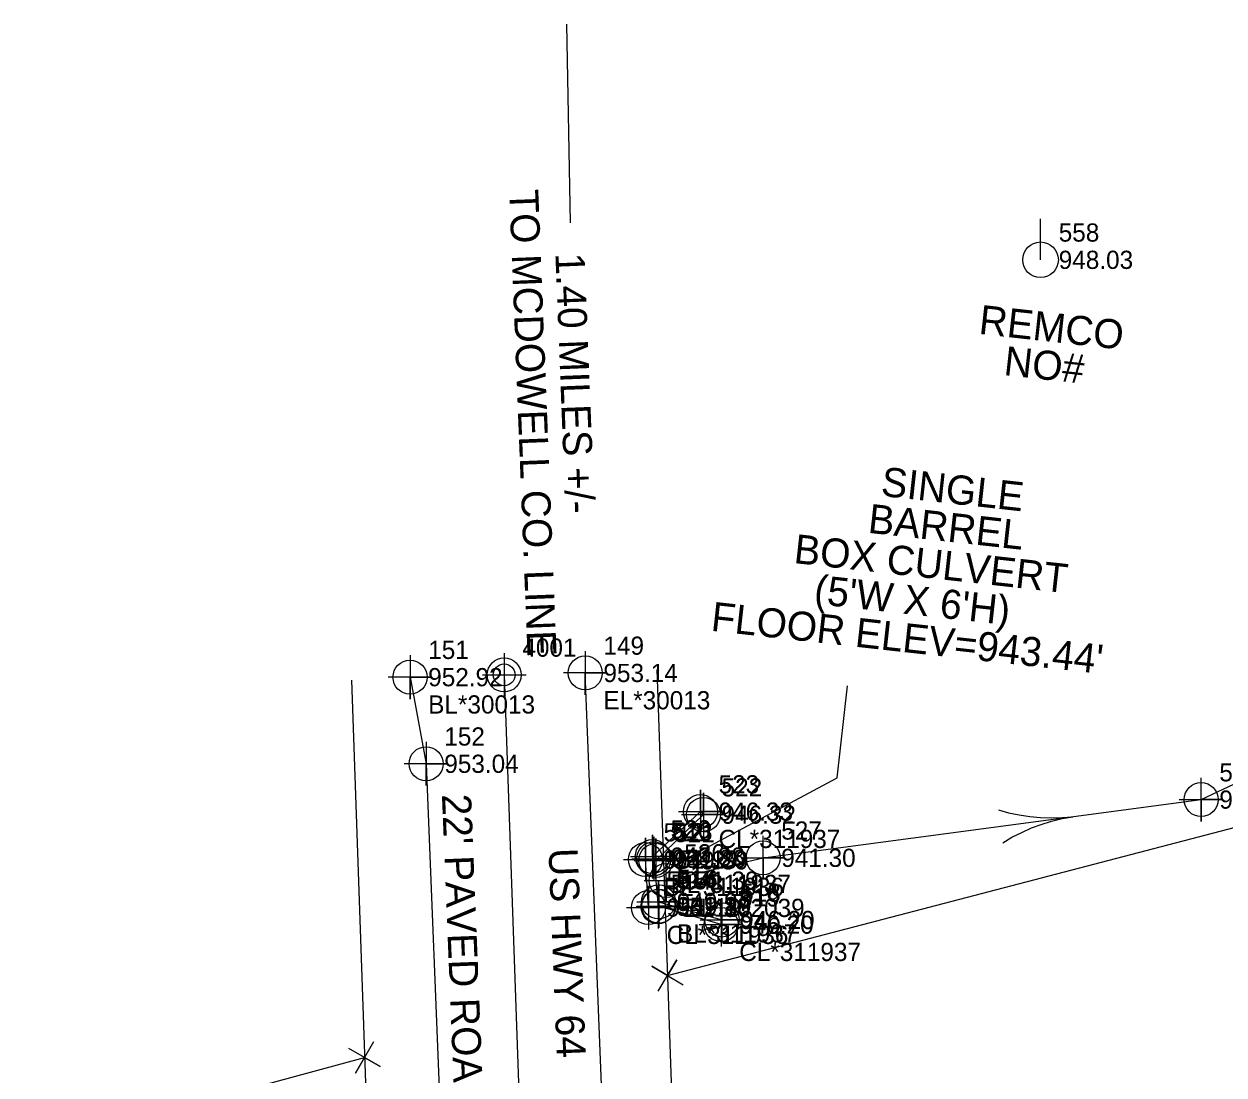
# Model space of a CAD drawing. Extents: x 1150279 to 1151282, y 654632 to 657999.
# Drawn here: x 1150502.6 to 1150667.5, y 657176.2 to 657320.6 of the extents above; entities that cross this region are included whole.
import ezdxf

# ---------------------------------------------------------------- set-up
doc = ezdxf.new("R2010")
doc.units = 0
for name, color, linetype in [('COGO Default Chain', 7, 'Continuous'), ('Cogo Default Point CELL', 7, 'Continuous'), ('COGO Default Point Number', 7, 'Continuous'), ('Exist Horizontal Alignment', 7, 'Continuous'), ('Exist Horizontal Alignment Station Label', 7, 'Continuous'), ('Exist Hydro Stream Flow Arrow CELL', 7, 'Continuous'), ('Exist Hydro Stream or Body of Water', 7, 'Continuous'), ('Exist Hydro Stream or Body of Water Cogo Comment', 7, 'Continuous'), ('Exist Hydro Stream or Body of Water Cogo Elevation', 7, 'Continuous'), ('Exist Hydro Stream or Body of Water Cogo Number', 7, 'Continuous'), ('Exist Hydro Stream or Body of Water Cogo Point CELL', 7, 'Continuous'), ('Exist Property Corner CELL', 7, 'Continuous'), ('Exist Property Line', 7, 'Continuous'), ('Exist Right of Way Line', 7, 'Continuous'), ('Exist Roads EOP', 7, 'Continuous'), ('Exist Roads EOP Cogo Comment', 7, 'Continuous'), ('Exist Roads EOP Cogo Elevation', 7, 'Continuous'), ('Exist Roads EOP Cogo Number', 7, 'Continuous'), ('Exist Roads EOP Cogo Point CELL', 7, 'Continuous'), ('Exist Roads EOP Leader', 7, 'Continuous'), ('Exist Roads EOP Text', 7, 'Continuous'), ('Exist Structure Major Bridge WW', 7, 'Continuous'), ('Exist Structure Major Bridge WW Cogo Comment', 7, 'Continuous'), ('Exist Structure Major Bridge WW Cogo Elevation', 7, 'Continuous'), ('Exist Structure Major Bridge WW Cogo Number', 7, 'Continuous'), ('Exist Structure Major Bridge WW Cogo Point CELL', 7, 'Continuous'), ('Exist Structure Major Bridge WW Leader', 7, 'Continuous'), ('Exist Structure Major Bridge WW Text', 7, 'Continuous'), ('Exist Utilities Power Pole CELL', 7, 'Continuous'), ('Exist Utilities Power Pole Cogo Elevation', 7, 'Continuous'), ('Exist Utilities Power Pole Cogo Number', 7, 'Continuous'), ('Exist Utilities Power Pole Text', 7, 'Continuous')]:
    doc.layers.add(name, color=color, linetype=linetype)

msp = doc.modelspace()

# ---------------------------------------------------------------- linework, layer by layer
at = {"layer": 'COGO Default Chain'}
msp.add_line((1150568.54, 657231.15), (1150575.96, 657017.52), dxfattribs=at)
at = {"layer": 'Cogo Default Point CELL'}
for points in [[(1150568.54, 657234.15), (1150568.54, 657231.15)], [(1150565.54, 657231.15), (1150568.54, 657231.15)], [(1150568.54, 657231.15), (1150571.54, 657231.15)], [(1150568.54, 657231.15), (1150568.54, 657228.15)]]:
    msp.add_lwpolyline(points, dxfattribs=at)
msp.add_circle((1150568.54, 657231.15), 2.34, dxfattribs=at)
at = {"layer": 'Exist Horizontal Alignment'}
msp.add_line((1150568.54, 657231.15), (1150575.96, 657017.52), dxfattribs=at)
at = {"layer": 'Exist Horizontal Alignment Station Label'}
msp.add_circle((1150568.54, 657231.15), 1.5, dxfattribs=at)
at = {"layer": 'Exist Hydro Stream Flow Arrow CELL'}
msp.add_line((1150641.7, 657211.02), (1150641.7, 657211.02), dxfattribs=at)
for points in [[(1150636.45, 657212.62), (1150637.85, 657212.21), (1150639.32, 657211.93), (1150640.78, 657211.69), (1150642.22, 657211.56), (1150643.7, 657211.52), (1150645.2, 657211.56), (1150646.66, 657211.67)], [(1150637.05, 657208.09), (1150638.3, 657208.86), (1150639.65, 657209.51), (1150640.99, 657210.13), (1150642.35, 657210.62), (1150643.77, 657211.05), (1150645.22, 657211.41), (1150646.66, 657211.67)]]:
    msp.add_lwpolyline(points, dxfattribs=at)
at = {"layer": 'Exist Hydro Stream or Body of Water'}
msp.add_lwpolyline([(1150590.78, 657202.89), (1150604.11, 657206.02), (1150664.31, 657214.02), (1150690.76, 657226.46), (1150708.05, 657225.68), (1150725.14, 657224.28), (1150732.8, 657228.83), (1150747.96, 657235.28), (1150766.11, 657239.26), (1150781.02, 657229.67)], dxfattribs=at)
at = {"layer": 'Exist Hydro Stream or Body of Water Cogo Point CELL'}
for points in [[(1150661.31, 657214.02), (1150667.31, 657214.02), (1150664.31, 657214.02), (1150664.31, 657211.02), (1150664.31, 657217.02)], [(1150601.11, 657206.02), (1150607.11, 657206.02), (1150604.11, 657206.02), (1150604.11, 657203.02), (1150604.11, 657209.02)], [(1150587.78, 657202.89), (1150593.78, 657202.89), (1150590.78, 657202.89), (1150590.78, 657199.89), (1150590.78, 657205.89)]]:
    msp.add_lwpolyline(points, dxfattribs=at)
for centre in [(1150664.31, 657214.02), (1150604.11, 657206.02), (1150590.78, 657202.89)]:
    msp.add_circle(centre, 2.34, dxfattribs=at)
at = {"layer": 'Exist Property Corner CELL'}
for p, q in [((1150590.98, 657189.86), (1150590.98, 657189.86)), ((1150549.35, 657178.59), (1150549.35, 657178.59))]:
    msp.add_line(p, q, dxfattribs=at)
for points in [[(1150589.72, 657187.7), (1150592.25, 657192.01), (1150590.98, 657189.86), (1150588.83, 657191.12), (1150593.14, 657188.59)], [(1150550.6, 657180.75), (1150548.11, 657176.42), (1150549.35, 657178.59), (1150551.52, 657177.34), (1150547.18, 657179.83)]]:
    msp.add_lwpolyline(points, dxfattribs=at)
at = {"layer": 'Exist Property Line'}
for p, q in [((1150590.98, 657189.86), (1150860.41, 657260.23)), ((1150281.26, 657106.12), (1150549.35, 657178.59))]:
    msp.add_line(p, q, dxfattribs=at)
at = {"layer": 'Exist Right of Way Line'}
for p, q in [((1150589.52, 657231.88), (1150591.75, 657167.81)), ((1150547.55, 657230.42), (1150554.98, 657016.79))]:
    msp.add_line(p, q, dxfattribs=at)
at = {"layer": 'Exist Roads EOP'}
msp.add_line((1150582.24, 657166.76), (1150579.68, 657231.42), dxfattribs=at)
msp.add_lwpolyline([(1150555.6, 657230.84), (1150557.81, 657218.94), (1150559.89, 657167.47), (1150561.73, 657122.25), (1150563.33, 657070.95), (1150564.64, 657020.93), (1150563.6, 657016.73)], dxfattribs=at)
at = {"layer": 'Exist Roads EOP Cogo Point CELL'}
for points in [[(1150555.6, 657233.84), (1150555.6, 657227.84), (1150555.6, 657230.84), (1150558.6, 657230.84), (1150552.6, 657230.84)], [(1150579.68, 657234.42), (1150579.68, 657228.42), (1150579.68, 657231.42), (1150582.68, 657231.42), (1150576.68, 657231.42)], [(1150557.81, 657221.94), (1150557.81, 657215.94), (1150557.81, 657218.94), (1150560.81, 657218.94), (1150554.81, 657218.94)]]:
    msp.add_lwpolyline(points, dxfattribs=at)
for centre in [(1150579.68, 657231.42), (1150555.6, 657230.84), (1150557.81, 657218.94)]:
    msp.add_circle(centre, 2.34, dxfattribs=at)
at = {"layer": 'Exist Roads EOP Leader'}
msp.add_line((1150577.09, 657320.58), (1150577.59, 657293.28), dxfattribs=at)
at = {"layer": 'Exist Structure Major Bridge WW'}
for points in [[(1150588.9, 657206.19), (1150589.39, 657205.67), (1150595.91, 657211.95), (1150595.5, 657212.37), (1150588.9, 657206.19)], [(1150587.94, 657205.78), (1150589.1, 657205.89), (1150589.68, 657199.31), (1150588.36, 657199.18), (1150587.94, 657205.78)], [(1150589.79, 657199.38), (1150589.76, 657199.96), (1150598.47, 657197.48), (1150598.34, 657196.84), (1150589.79, 657199.38)]]:
    msp.add_lwpolyline(points, dxfattribs=at)
at = {"layer": 'Exist Structure Major Bridge WW Cogo Point CELL'}
for points in [[(1150592.5, 657212.37), (1150598.5, 657212.37), (1150595.5, 657212.37), (1150595.5, 657215.37), (1150595.5, 657209.37)], [(1150592.91, 657211.95), (1150598.91, 657211.95), (1150595.91, 657211.95), (1150595.91, 657214.95), (1150595.91, 657208.95)], [(1150584.94, 657205.78), (1150590.94, 657205.78), (1150587.94, 657205.78), (1150587.94, 657208.78), (1150587.94, 657202.78)], [(1150585.9, 657206.19), (1150591.9, 657206.19), (1150588.9, 657206.19), (1150588.9, 657209.19), (1150588.9, 657203.19)], [(1150586.1, 657205.89), (1150592.1, 657205.89), (1150589.1, 657205.89), (1150589.1, 657208.89), (1150589.1, 657202.89)], [(1150586.39, 657205.67), (1150592.39, 657205.67), (1150589.39, 657205.67), (1150589.39, 657208.67), (1150589.39, 657202.67)], [(1150585.36, 657199.18), (1150591.36, 657199.18), (1150588.36, 657199.18), (1150588.36, 657202.18), (1150588.36, 657196.18)], [(1150586.68, 657199.31), (1150592.68, 657199.31), (1150589.68, 657199.31), (1150589.68, 657202.31), (1150589.68, 657196.31)], [(1150586.76, 657199.96), (1150592.76, 657199.96), (1150589.76, 657199.96), (1150589.76, 657202.96), (1150589.76, 657196.96)], [(1150586.79, 657199.38), (1150592.79, 657199.38), (1150589.79, 657199.38), (1150589.79, 657202.38), (1150589.79, 657196.38)], [(1150595.47, 657197.48), (1150601.47, 657197.48), (1150598.47, 657197.48), (1150598.47, 657200.48), (1150598.47, 657194.48)], [(1150595.34, 657196.84), (1150601.34, 657196.84), (1150598.34, 657196.84), (1150598.34, 657199.84), (1150598.34, 657193.84)]]:
    msp.add_lwpolyline(points, dxfattribs=at)
for centre in [(1150595.5, 657212.37), (1150595.91, 657211.95), (1150588.9, 657206.19), (1150587.94, 657205.78), (1150589.1, 657205.89), (1150589.39, 657205.67), (1150589.76, 657199.96), (1150588.36, 657199.18), (1150589.68, 657199.31), (1150589.79, 657199.38), (1150598.34, 657196.84), (1150598.47, 657197.48)]:
    msp.add_circle(centre, 2.34, dxfattribs=at)
at = {"layer": 'Exist Structure Major Bridge WW Leader'}
msp.add_lwpolyline([(1150592.31, 657205.26), (1150614.31, 657217.01), (1150615.71, 657229.63)], dxfattribs=at)
at = {"layer": 'Exist Utilities Power Pole CELL'}
for q in [(1150642.24, 657293.8), (1150642.24, 657288.18)]:
    msp.add_line((1150642.24, 657288.18), q, dxfattribs=at)
msp.add_circle((1150642.24, 657288.18), 2.45, dxfattribs=at)

# ---------------------------------------------------------------- texts
at = {"layer": 'COGO Default Point Number'}
msp.add_text('4001', height=2.5, dxfattribs=at).set_placement((1150571.04, 657233.65))
at = {"layer": 'Exist Hydro Stream or Body of Water Cogo Comment'}
msp.add_text('BL*362039', height=2.5, dxfattribs=at).set_placement((1150593.28, 657197.89))
at = {"layer": 'Exist Hydro Stream or Body of Water Cogo Elevation'}
for s, p in [('939.69', (1150666.81, 657212.77)), ('941.30', (1150606.61, 657204.77)), ('941.39', (1150593.28, 657201.64))]:
    msp.add_text(s, height=2.5, dxfattribs=at).set_placement(p)
at = {"layer": 'Exist Hydro Stream or Body of Water Cogo Number'}
for s, p in [('531', (1150666.81, 657216.52)), ('527', (1150606.61, 657208.52)), ('526', (1150593.28, 657205.39))]:
    msp.add_text(s, height=2.5, dxfattribs=at).set_placement(p)
at = {"layer": 'Exist Roads EOP Cogo Comment'}
for s, p in [('BL*30013', (1150558.1, 657225.84)), ('EL*30013', (1150582.18, 657226.42))]:
    msp.add_text(s, height=2.5, dxfattribs=at).set_placement(p)
at = {"layer": 'Exist Roads EOP Cogo Elevation'}
for s, p in [('952.92', (1150558.1, 657229.59)), ('953.14', (1150582.18, 657230.17)), ('953.04', (1150560.31, 657217.69))]:
    msp.add_text(s, height=2.5, dxfattribs=at).set_placement(p)
at = {"layer": 'Exist Roads EOP Cogo Number'}
for s, p in [('151', (1150558.1, 657233.34)), ('149', (1150582.18, 657233.92)), ('152', (1150560.31, 657221.44))]:
    msp.add_text(s, height=2.5, dxfattribs=at).set_placement(p)
at = {"layer": 'Exist Roads EOP Text'}
for s, rotation, p in [('TO MCDOWELL CO. LINE', 272.2625, (1150569.22, 657297.77)), ('1.40 MILES +/-', 272.2625, (1150575.57, 657289.05)), ("22' PAVED ROADWAY", 272.3134, (1150559.98, 657214.72)), ('US HWY 64', 272.2625, (1150574.63, 657207.28))]:
    msp.add_text(s, height=4, rotation=rotation, dxfattribs=at).set_placement(p)
at = {"layer": 'Exist Structure Major Bridge WW Cogo Comment'}
for s, p in [('CL*311937', (1150598, 657207.37)), ('BL*311937', (1150591.4, 657201.19)), ('BL*311936', (1150590.44, 657200.78)), ('CL*311936', (1150590.86, 657194.18)), ('BL*311937', (1150592.29, 657194.38)), ('CL*311937', (1150600.84, 657191.84))]:
    msp.add_text(s, height=2.5, dxfattribs=at).set_placement(p)
at = {"layer": 'Exist Structure Major Bridge WW Cogo Elevation'}
for s, p in [('946.33', (1150598, 657211.12)), ('946.32', (1150598.41, 657210.7)), ('951.19', (1150590.44, 657204.53)), ('949.88', (1150591.4, 657204.94)), ('951.20', (1150591.6, 657204.64)), ('949.89', (1150591.89, 657204.42)), ('951.19', (1150590.86, 657197.93)), ('951.18', (1150592.18, 657198.06)), ('949.97', (1150592.26, 657198.71)), ('949.89', (1150592.29, 657198.13)), ('946.20', (1150600.97, 657196.23)), ('946.20', (1150600.84, 657195.59))]:
    msp.add_text(s, height=2.5, dxfattribs=at).set_placement(p)
at = {"layer": 'Exist Structure Major Bridge WW Cogo Number'}
for s, p in [('523', (1150598, 657214.87)), ('522', (1150598.41, 657214.45)), ('512', (1150590.44, 657208.28)), ('520', (1150591.4, 657208.69)), ('513', (1150591.6, 657208.39)), ('521', (1150591.89, 657208.17)), ('515', (1150590.86, 657201.68)), ('514', (1150592.18, 657201.81)), ('517', (1150592.26, 657202.46)), ('516', (1150592.29, 657201.88)), ('518', (1150600.97, 657199.98)), ('519', (1150600.84, 657199.34))]:
    msp.add_text(s, height=2.5, dxfattribs=at).set_placement(p)
at = {"layer": 'Exist Structure Major Bridge WW Text'}
for s, p in [('SINGLE', (1150620.2, 657255.77)), ('BARREL', (1150618.42, 657250.69)), ('BOX CULVERT', (1150608.23, 657246.53)), ("(5'W X 6'H)", (1150611, 657240.94)), ("FLOOR ELEV=943.44'", (1150596.84, 657237.23))]:
    msp.add_text(s, height=4, rotation=353.6867, dxfattribs=at).set_placement(p)
at = {"layer": 'Exist Utilities Power Pole Cogo Elevation'}
msp.add_text('948.03', height=2.5, dxfattribs=at).set_placement((1150644.74, 657286.93))
at = {"layer": 'Exist Utilities Power Pole Cogo Number'}
msp.add_text('558', height=2.5, dxfattribs=at).set_placement((1150644.74, 657290.68))
at = {"layer": 'Exist Utilities Power Pole Text'}
for s, p in [('REMCO', (1150633.65, 657278.02)), ('NO#', (1150637.08, 657272.36))]:
    msp.add_text(s, height=4, rotation=353.6867, dxfattribs=at).set_placement(p)

doc.saveas('drawing.dxf')
